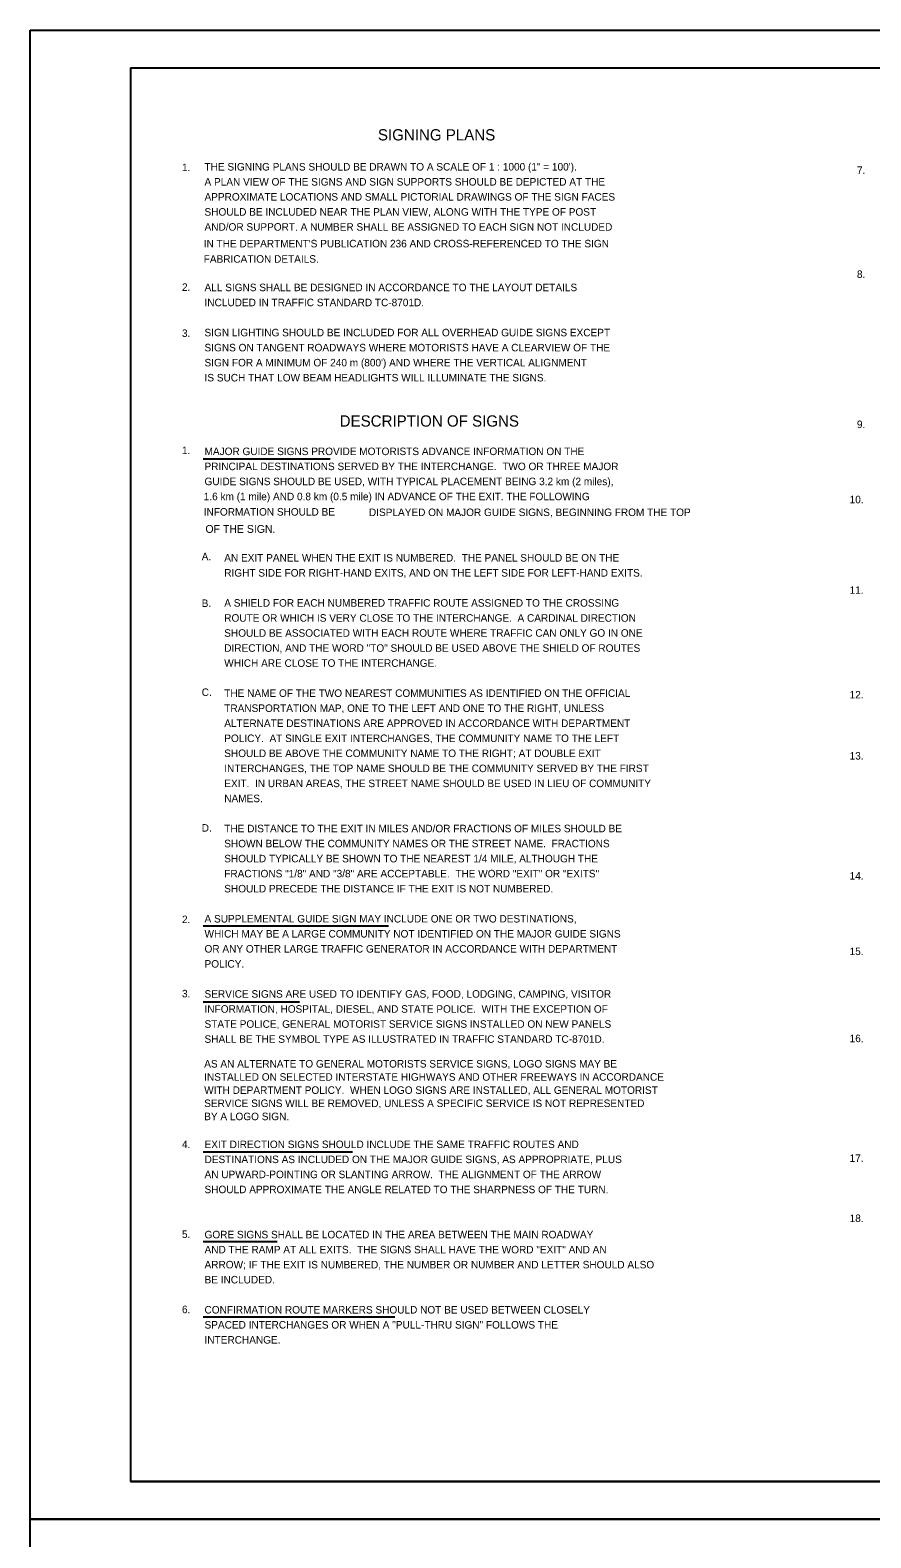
# Model space of a CAD drawing. Extents: x 644898 to 648326, y 298294 to 300670.
# Drawn here: x 644898 to 645234, y 300069 to 300670 of the extents above; entities that cross this region are included whole.
import ezdxf

# ---------------------------------------------------------------- set-up
doc = ezdxf.new("R2010")
doc.units = 0
for name, color, linetype in [('1', 7, 'Continuous'), ('2', 7, 'Continuous'), ('XCS-GRID-MIN', 7, 'Continuous')]:
    doc.layers.add(name, color=color, linetype=linetype)

msp = doc.modelspace()

# ---------------------------------------------------------------- linework, layer by layer
at = {"layer": '1'}
for p, q in [((644938.32, 300655.49), (645724.32, 300655.49)), ((644938.32, 300655.49), (644938.32, 300091.49)), ((645724.32, 300091.49), (644938.32, 300091.49)), ((644938.32, 300091.49), (645524.32, 300091.49))]:
    msp.add_line(p, q, dxfattribs=at)
at = {"layer": '2'}
for p, q in [((644967.41, 300499.46), (645018.04, 300499.46)), ((644967.41, 300313.12), (645041.28, 300313.12)), ((644967.41, 300282.87), (645005.78, 300282.87)), ((644967.41, 300222.99), (645026.91, 300222.99)), ((644967.41, 300187.24), (644996.91, 300187.24)), ((644967.41, 300157.12), (645043.91, 300157.12))]:
    msp.add_line(p, q, dxfattribs=at)
at = {"layer": 'XCS-GRID-MIN'}
for points in [[(644898.32, 300670.49), (645739.32, 300670.49), (645739.32, 300076.49), (644898.32, 300076.49)], [(644898.32, 300076.49), (645739.32, 300076.49), (645739.32, 299482.49), (644898.32, 299482.49)]]:
    msp.add_lwpolyline(points, close=True, dxfattribs=at)

# ---------------------------------------------------------------- texts
at = {"layer": '2'}
for s, height, p in [('SIGNING PLANS', 4.5, (645037.1, 300626.49)), ('1. ', 3, (644958.91, 300614.24)), ('THE SIGNING PLANS SHOULD BE DRAWN TO A SCALE OF 1 : 1000 (1" = 100\').', 3, (644967.91, 300614.49)), ('7.   ', 3, (645228.25, 300613.11)), ('A PLAN VIEW OF THE SIGNS AND SIGN SUPPORTS SHOULD BE DEPICTED AT THE ', 3, (644967.91, 300608.49)), ('APPROXIMATE LOCATIONS AND SMALL PICTORIAL DRAWINGS OF THE SIGN FACES ', 3, (644967.91, 300602.49)), ('AND/OR SUPPORT. A NUMBER SHALL BE ASSIGNED TO EACH SIGN NOT INCLUDED ', 3, (644967.91, 300590.49)), ('SHOULD BE INCLUDED NEAR THE PLAN VIEW, ALONG WITH THE TYPE OF POST', 3, (644967.91, 300596.49)), ("IN THE DEPARTMENT'S PUBLICATION 236 AND CROSS-REFERENCED TO THE SIGN", 3, (644967.59, 300583.84)), ('FABRICATION DETAILS.', 3, (644967.59, 300577.71)), ('8.   ', 3, (645228.25, 300571.62)), ('2.   ', 3, (644958.91, 300566.48)), ('ALL SIGNS SHALL BE DESIGNED IN ACCORDANCE TO THE LAYOUT DETAILS', 3, (644967.91, 300566.35)), ('INCLUDED IN TRAFFIC STANDARD TC-8701D.', 3, (644967.91, 300560.35)), ('3.   ', 3, (644958.91, 300548.1)), ('SIGN LIGHTING SHOULD BE INCLUDED FOR ALL OVERHEAD GUIDE SIGNS EXCEPT', 3, (644967.91, 300548.35)), ('SIGNS ON TANGENT ROADWAYS WHERE MOTORISTS HAVE A CLEARVIEW OF THE', 3, (644967.91, 300542.35)), ("SIGN FOR A MINIMUM OF 240 m (800') AND WHERE THE VERTICAL ALIGNMENT ", 3, (644967.91, 300536.35)), ('IS SUCH THAT LOW BEAM HEADLIGHTS WILL ILLUMINATE THE SIGNS.', 3, (644967.91, 300530.35)), ('DESCRIPTION OF SIGNS', 4.5, (645021.84, 300512.32)), ('9.   ', 3, (645228.25, 300511.74)), ('1.  ', 3, (644958.91, 300501.34)), ('MAJOR GUIDE SIGNS PROVIDE MOTORISTS ADVANCE INFORMATION ON THE', 3, (644967.91, 300500.96)), ('PRINCIPAL DESTINATIONS SERVED BY THE INTERCHANGE.  TWO OR THREE MAJOR', 3, (644967.91, 300494.96)), ('GUIDE SIGNS SHOULD BE USED, WITH TYPICAL PLACEMENT BEING 3.2 km (2 miles),', 3, (644967.91, 300488.96)), ('1.6 km (1 mile) AND 0.8 km (0.5 mile) IN ADVANCE OF THE EXIT. THE FOLLOWING', 3, (644967.59, 300482.95)), ('INFORMATION SHOULD BE', 3, (644967.59, 300476.82)), ('DISPLAYED ON MAJOR GUIDE SIGNS, BEGINNING FROM THE TOP', 3, (645033.52, 300476.64)), ('10.', 3, (645225.33, 300481.74)), ('OF THE SIGN.', 3.1342, (644968.27, 300469.94)), ('A. ', 3, (644966.78, 300458.99)), ('AN EXIT PANEL WHEN THE EXIT IS NUMBERED.  THE PANEL SHOULD BE ON THE', 3, (644975.78, 300458.49)), ('RIGHT SIDE FOR RIGHT-HAND EXITS, AND ON THE LEFT SIDE FOR LEFT-HAND EXITS.', 3, (644975.78, 300452.49)), ('B.  ', 3, (644966.78, 300440.37)), ('A SHIELD FOR EACH NUMBERED TRAFFIC ROUTE ASSIGNED TO THE CROSSING', 3, (644975.78, 300440.49)), ('11.', 3, (645225.33, 300445.62)), ('ROUTE OR WHICH IS VERY CLOSE TO THE INTERCHANGE.  A CARDINAL DIRECTION', 3, (644975.78, 300434.49)), ('SHOULD BE ASSOCIATED WITH EACH ROUTE WHERE TRAFFIC CAN ONLY GO IN ONE', 3, (644975.78, 300428.49)), ('DIRECTION, AND THE WORD "TO" SHOULD BE USED ABOVE THE SHIELD OF ROUTES', 3, (644975.78, 300422.49)), ('WHICH ARE CLOSE TO THE INTERCHANGE.', 3, (644975.78, 300416.49)), ('C.   ', 3, (644966.78, 300404.87)), ('THE NAME OF THE TWO NEAREST COMMUNITIES AS IDENTIFIED ON THE OFFICIAL', 3, (644975.78, 300404.49)), ('TRANSPORTATION MAP, ONE TO THE LEFT AND ONE TO THE RIGHT, UNLESS', 3, (644975.78, 300398.49)), ('12.', 3, (645225.33, 300403.87)), ('ALTERNATE DESTINATIONS ARE APPROVED IN ACCORDANCE WITH DEPARTMENT', 3, (644975.78, 300392.49)), ('POLICY.  AT SINGLE EXIT INTERCHANGES, THE COMMUNITY NAME TO THE LEFT', 3, (644975.78, 300386.49)), ('SHOULD BE ABOVE THE COMMUNITY NAME TO THE RIGHT; AT DOUBLE EXIT', 3, (644975.78, 300380.49)), ('INTERCHANGES, THE TOP NAME SHOULD BE THE COMMUNITY SERVED BY THE FIRST', 3, (644975.78, 300374.49)), ('13.', 3, (645225.33, 300379.49)), ('EXIT.  IN URBAN AREAS, THE STREET NAME SHOULD BE USED IN LIEU OF COMMUNITY', 3, (644975.78, 300368.49)), ('NAMES.', 3, (644975.78, 300362.49)), ('D.   ', 3, (644966.78, 300350.74)), ('THE DISTANCE TO THE EXIT IN MILES AND/OR FRACTIONS OF MILES SHOULD BE', 3, (644975.78, 300350.49)), ('SHOWN BELOW THE COMMUNITY NAMES OR THE STREET NAME.  FRACTIONS', 3, (644975.78, 300344.49)), ('SHOULD TYPICALLY BE SHOWN TO THE NEAREST 1/4 MILE, ALTHOUGH THE', 3, (644975.78, 300338.49)), ('FRACTIONS "1/8" AND "3/8" ARE ACCEPTABLE.  THE WORD "EXIT" OR "EXITS"', 3, (644975.78, 300332.49)), ('SHOULD PRECEDE THE DISTANCE IF THE EXIT IS NOT NUMBERED.', 3, (644975.78, 300326.49)), ('14.', 3, (645225.33, 300331.62)), ('2.  ', 3, (644958.91, 300314.24)), ('A SUPPLEMENTAL GUIDE SIGN MAY INCLUDE ONE OR TWO DESTINATIONS,', 3, (644967.91, 300314.49)), ('WHICH MAY BE A LARGE COMMUNITY NOT IDENTIFIED ON THE MAJOR GUIDE SIGNS', 3, (644967.91, 300308.49)), ('OR ANY OTHER LARGE TRAFFIC GENERATOR IN ACCORDANCE WITH DEPARTMENT', 3, (644967.91, 300302.49)), ('POLICY.', 3, (644967.91, 300296.49)), ('15.', 3, (645225.33, 300301.49)), ('3.  ', 3, (644958.91, 300284.62)), ('SERVICE SIGNS ARE USED TO IDENTIFY GAS, FOOD, LODGING, CAMPING, VISITOR', 3, (644967.91, 300284.49)), ('INFORMATION, HOSPITAL, DIESEL, AND STATE POLICE.  WITH THE EXCEPTION OF', 3, (644967.91, 300278.49)), ('STATE POLICE, GENERAL MOTORIST SERVICE SIGNS INSTALLED ON NEW PANELS', 3, (644967.91, 300272.49)), ('SHALL BE THE SYMBOL TYPE AS ILLUSTRATED IN TRAFFIC STANDARD TC-8701D.', 3, (644967.91, 300266.49)), ('16.   ', 3, (645225.33, 300266.74)), ('AS AN ALTERNATE TO GENERAL MOTORISTS SERVICE SIGNS, LOGO SIGNS MAY BE', 3, (644967.78, 300256.62)), ('INSTALLED ON SELECTED INTERSTATE HIGHWAYS AND OTHER FREEWAYS IN ACCORDANCE', 3, (644967.78, 300251.37)), ('WITH DEPARTMENT POLICY.  WHEN LOGO SIGNS ARE INSTALLED, ALL GENERAL MOTORIST', 3, (644967.78, 300246.12)), ('SERVICE SIGNS WILL BE REMOVED, UNLESS A SPECIFIC SERVICE IS NOT REPRESENTED', 3, (644967.78, 300240.87)), ('BY A LOGO SIGN.', 3, (644967.78, 300235.62)), ('4.  ', 3, (644958.91, 300224.49)), ('EXIT DIRECTION SIGNS SHOULD INCLUDE THE SAME TRAFFIC ROUTES AND', 3, (644967.91, 300224.49)), ('DESTINATIONS AS INCLUDED ON THE MAJOR GUIDE SIGNS, AS APPROPRIATE, PLUS', 3, (644967.91, 300218.49)), ('17.   ', 3, (645225.33, 300218.99)), ('AN UPWARD-POINTING OR SLANTING ARROW.  THE ALIGNMENT OF THE ARROW', 3, (644967.91, 300212.49)), ('SHOULD APPROXIMATE THE ANGLE RELATED TO THE SHARPNESS OF THE TURN.', 3, (644967.91, 300206.49)), ('18.', 3, (645225.33, 300194.99)), ('5.  ', 3, (644958.91, 300188.62)), ('GORE SIGNS SHALL BE LOCATED IN THE AREA BETWEEN THE MAIN ROADWAY', 3, (644967.91, 300188.49)), ('AND THE RAMP AT ALL EXITS.  THE SIGNS SHALL HAVE THE WORD "EXIT" AND AN', 3, (644967.91, 300182.49)), ('ARROW; IF THE EXIT IS NUMBERED, THE NUMBER OR NUMBER AND LETTER SHOULD ALSO', 3, (644967.91, 300176.49)), ('BE INCLUDED.', 3, (644967.91, 300170.49)), ('6. ', 3, (644958.91, 300158.62)), ('CONFIRMATION ROUTE MARKERS SHOULD NOT BE USED BETWEEN CLOSELY', 3, (644967.91, 300158.49)), ('SPACED INTERCHANGES OR WHEN A "PULL-THRU SIGN" FOLLOWS THE', 3, (644967.91, 300152.49)), ('INTERCHANGE.', 3, (644967.91, 300146.49))]:
    msp.add_text(s, height=height, dxfattribs=at).set_placement(p)

doc.saveas('drawing.dxf')
